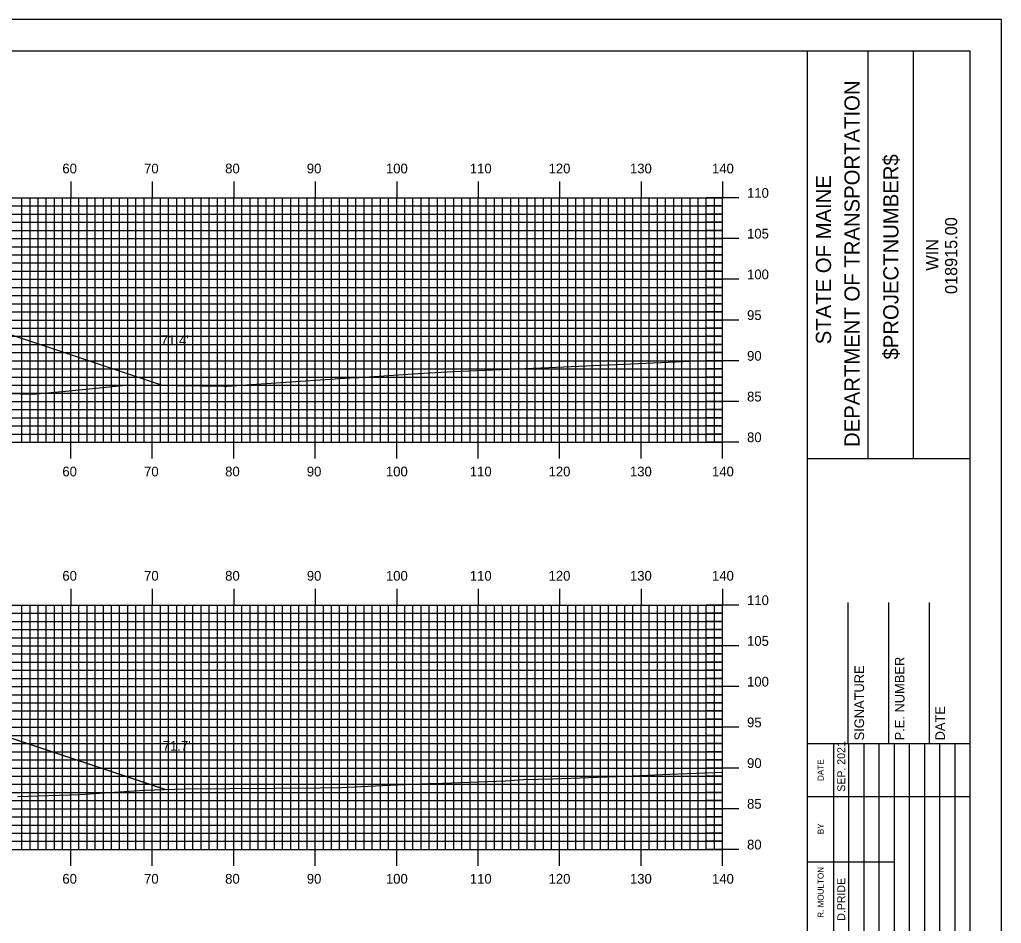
# Model space of a CAD drawing. Extents: x 1762184 to 1762528, y 442591 to 442811.
# Drawn here: x 1762404 to 1762524.5, y 442699.6 to 442810.5 of the extents above; entities that cross this region are included whole.
import ezdxf

# ---------------------------------------------------------------- set-up
doc = ezdxf.new("R2010")
doc.units = 0
for name, color, linetype in [('BORDER', 7, 'Continuous'), ('D_Roadway_Centerline', 7, 'Continuous'), ('D_Roadway_SlopeLines', 7, 'Continuous'), ('D_Text_Standard', 7, 'Continuous'), ('H_V ANNOTATION', 7, 'Continuous'), ('MAJOR', 7, 'Continuous'), ('MINOR', 7, 'Continuous'), ('PLOT BOUNDARY', 7, 'Continuous'), ('S_Roadway_Centerline', 7, 'Continuous')]:
    doc.layers.add(name, color=color, linetype=linetype)

msp = doc.modelspace()

# ---------------------------------------------------------------- linework, layer by layer
at = {"layer": 'BORDER'}
for p, q in [((1762500.67, 442596.67), (1762500.67, 442806.67)), ((1762508.12, 442756.66), (1762508.12, 442806.66)), ((1762513.71, 442756.66), (1762513.71, 442806.66)), ((1762500.67, 442756.65), (1762520.67, 442756.65)), ((1762505.67, 442721.67), (1762505.67, 442738.97)), ((1762510.67, 442721.67), (1762510.67, 442738.97)), ((1762515.67, 442721.67), (1762515.67, 442738.97)), ((1762500.67, 442721.67), (1762520.67, 442721.67))]:
    msp.add_line(p, q, dxfattribs=at)
msp.add_lwpolyline([(1762200.67, 442596.67), (1762520.67, 442596.67), (1762520.67, 442806.67), (1762200.67, 442806.67)], close=True, dxfattribs=at)
for points in [[(1762503.9, 442715.17), (1762503.9, 442721.67)], [(1762505.76, 442686.68), (1762505.76, 442721.67)], [(1762507.62, 442721.67), (1762507.62, 442686.68)], [(1762509.49, 442686.68), (1762509.49, 442721.67)], [(1762511.35, 442686.68), (1762511.35, 442721.67)], [(1762513.21, 442686.68), (1762513.21, 442721.67)], [(1762515.08, 442686.68), (1762515.08, 442721.67)], [(1762516.94, 442686.68), (1762516.94, 442721.67)], [(1762518.8, 442686.68), (1762518.8, 442721.67)], [(1762503.9, 442686.68), (1762503.9, 442720.26)], [(1762500.67, 442715.17), (1762520.67, 442715.17)], [(1762500.67, 442707.17), (1762503.9, 442707.17)], [(1762503.9, 442707.17), (1762511.35, 442707.17)]]:
    msp.add_lwpolyline(points, dxfattribs=at)
at = {"layer": 'D_Roadway_Centerline'}
for points in [[(1762382.28, 442778.76), (1762418.67, 442766.63), (1762421.63, 442765.65), (1762421.63, 442765.65)], [(1762382.27, 442729.27), (1762420.68, 442716.46), (1762421.95, 442716.04)]]:
    msp.add_lwpolyline(points, dxfattribs=at)
at = {"layer": 'D_Roadway_SlopeLines'}
for points in [[(1762370.27, 442781.77), (1762382.27, 442778.77), (1762421.63, 442765.65)], [(1762370.27, 442732.27), (1762382.27, 442729.27), (1762421.95, 442716.04)]]:
    msp.add_lwpolyline(points, dxfattribs=at)
at = {"layer": 'MAJOR'}
for p, q in [((1762410.27, 442790.67), (1762410.27, 442788.67)), ((1762420.27, 442790.67), (1762420.27, 442788.67)), ((1762430.27, 442790.67), (1762430.27, 442788.67)), ((1762440.27, 442790.67), (1762440.27, 442788.67)), ((1762450.27, 442790.67), (1762450.27, 442788.67)), ((1762460.27, 442790.67), (1762460.27, 442788.67)), ((1762470.27, 442790.67), (1762470.27, 442788.67)), ((1762480.27, 442790.67), (1762480.27, 442788.67)), ((1762490.27, 442790.67), (1762490.27, 442788.67)), ((1762210.27, 442788.67), (1762490.27, 442788.67)), ((1762210.27, 442788.67), (1762490.27, 442788.67)), ((1762410.27, 442758.67), (1762410.27, 442788.67)), ((1762420.27, 442758.67), (1762420.27, 442788.67)), ((1762430.27, 442758.67), (1762430.27, 442788.67)), ((1762440.27, 442758.67), (1762440.27, 442788.67)), ((1762450.27, 442758.67), (1762450.27, 442788.67)), ((1762460.27, 442758.67), (1762460.27, 442788.67)), ((1762470.27, 442758.67), (1762470.27, 442788.67)), ((1762480.27, 442758.67), (1762480.27, 442788.67)), ((1762492.27, 442788.67), (1762488.26, 442788.67)), ((1762490.27, 442758.67), (1762490.27, 442788.67)), ((1762490.27, 442758.67), (1762490.27, 442788.67)), ((1762210.27, 442783.67), (1762490.27, 442783.67)), ((1762492.27, 442783.67), (1762488.26, 442783.67)), ((1762210.27, 442778.67), (1762490.27, 442778.67)), ((1762492.27, 442778.67), (1762488.26, 442778.67)), ((1762210.27, 442773.67), (1762490.27, 442773.67)), ((1762492.27, 442773.67), (1762488.26, 442773.67)), ((1762210.27, 442768.67), (1762490.27, 442768.67)), ((1762492.27, 442768.67), (1762488.26, 442768.67)), ((1762210.27, 442763.67), (1762490.27, 442763.67)), ((1762492.27, 442763.67), (1762488.26, 442763.67)), ((1762210.27, 442758.67), (1762490.27, 442758.67)), ((1762210.27, 442758.67), (1762490.27, 442758.67)), ((1762410.27, 442756.66), (1762410.27, 442758.67)), ((1762420.27, 442756.66), (1762420.27, 442758.67)), ((1762430.27, 442756.66), (1762430.27, 442758.67)), ((1762440.27, 442756.66), (1762440.27, 442758.67)), ((1762450.27, 442756.66), (1762450.27, 442758.67)), ((1762460.27, 442756.66), (1762460.27, 442758.67)), ((1762470.27, 442756.66), (1762470.27, 442758.67)), ((1762480.27, 442756.66), (1762480.27, 442758.67)), ((1762492.27, 442758.67), (1762488.26, 442758.67)), ((1762490.27, 442756.66), (1762490.27, 442758.67)), ((1762410.27, 442740.67), (1762410.27, 442738.67)), ((1762420.27, 442740.67), (1762420.27, 442738.67)), ((1762430.27, 442740.67), (1762430.27, 442738.67)), ((1762440.27, 442740.67), (1762440.27, 442738.67)), ((1762450.27, 442740.67), (1762450.27, 442738.67)), ((1762460.27, 442740.67), (1762460.27, 442738.67)), ((1762470.27, 442740.67), (1762470.27, 442738.67)), ((1762480.27, 442740.67), (1762480.27, 442738.67)), ((1762490.27, 442740.67), (1762490.27, 442738.67)), ((1762210.27, 442738.67), (1762490.27, 442738.67)), ((1762210.27, 442738.67), (1762490.27, 442738.67)), ((1762410.27, 442708.67), (1762410.27, 442738.67)), ((1762420.27, 442708.67), (1762420.27, 442738.67)), ((1762430.27, 442708.67), (1762430.27, 442738.67)), ((1762440.27, 442708.67), (1762440.27, 442738.67)), ((1762450.27, 442708.67), (1762450.27, 442738.67)), ((1762460.27, 442708.67), (1762460.27, 442738.67)), ((1762470.27, 442708.67), (1762470.27, 442738.67)), ((1762480.27, 442708.67), (1762480.27, 442738.67)), ((1762492.27, 442738.67), (1762488.26, 442738.67)), ((1762490.27, 442708.67), (1762490.27, 442738.67)), ((1762490.27, 442708.67), (1762490.27, 442738.67)), ((1762210.27, 442733.67), (1762490.27, 442733.67)), ((1762492.27, 442733.67), (1762488.26, 442733.67)), ((1762210.27, 442728.67), (1762490.27, 442728.67)), ((1762492.27, 442728.67), (1762488.26, 442728.67)), ((1762210.27, 442723.67), (1762490.27, 442723.67)), ((1762492.27, 442723.67), (1762488.26, 442723.67)), ((1762210.27, 442718.67), (1762490.27, 442718.67)), ((1762492.27, 442718.67), (1762488.26, 442718.67)), ((1762210.27, 442713.67), (1762490.27, 442713.67)), ((1762492.27, 442713.67), (1762488.26, 442713.67)), ((1762210.27, 442708.67), (1762490.27, 442708.67)), ((1762210.27, 442708.67), (1762490.27, 442708.67)), ((1762410.27, 442706.66), (1762410.27, 442708.67)), ((1762420.27, 442706.66), (1762420.27, 442708.67)), ((1762430.27, 442706.66), (1762430.27, 442708.67)), ((1762440.27, 442706.66), (1762440.27, 442708.67)), ((1762450.27, 442706.66), (1762450.27, 442708.67)), ((1762460.27, 442706.66), (1762460.27, 442708.67)), ((1762470.27, 442706.66), (1762470.27, 442708.67)), ((1762480.27, 442706.66), (1762480.27, 442708.67)), ((1762492.27, 442708.67), (1762488.26, 442708.67)), ((1762490.27, 442706.66), (1762490.27, 442708.67))]:
    msp.add_line(p, q, dxfattribs=at)
at = {"layer": 'MINOR'}
for p, q in [((1762210.27, 442787.67), (1762490.27, 442787.67)), ((1762404.27, 442758.67), (1762404.27, 442788.67)), ((1762405.27, 442758.67), (1762405.27, 442788.67)), ((1762406.27, 442758.67), (1762406.27, 442788.67)), ((1762407.27, 442758.67), (1762407.27, 442788.67)), ((1762408.27, 442758.67), (1762408.27, 442788.67)), ((1762409.27, 442758.67), (1762409.27, 442788.67)), ((1762411.27, 442758.67), (1762411.27, 442788.67)), ((1762412.27, 442758.67), (1762412.27, 442788.67)), ((1762413.27, 442758.67), (1762413.27, 442788.67)), ((1762414.27, 442758.67), (1762414.27, 442788.67)), ((1762415.27, 442758.67), (1762415.27, 442788.67)), ((1762416.27, 442758.67), (1762416.27, 442788.67)), ((1762417.27, 442758.67), (1762417.27, 442788.67)), ((1762418.27, 442758.67), (1762418.27, 442788.67)), ((1762419.27, 442758.67), (1762419.27, 442788.67)), ((1762421.27, 442758.67), (1762421.27, 442788.67)), ((1762422.27, 442758.67), (1762422.27, 442788.67)), ((1762423.27, 442758.67), (1762423.27, 442788.67)), ((1762424.27, 442758.67), (1762424.27, 442788.67)), ((1762425.27, 442758.67), (1762425.27, 442788.67)), ((1762426.27, 442758.67), (1762426.27, 442788.67)), ((1762427.27, 442758.67), (1762427.27, 442788.67)), ((1762428.27, 442758.67), (1762428.27, 442788.67)), ((1762429.27, 442758.67), (1762429.27, 442788.67)), ((1762431.27, 442758.67), (1762431.27, 442788.67)), ((1762432.27, 442758.67), (1762432.27, 442788.67)), ((1762433.27, 442758.67), (1762433.27, 442788.67)), ((1762434.27, 442758.67), (1762434.27, 442788.67)), ((1762435.27, 442758.67), (1762435.27, 442788.67)), ((1762436.27, 442758.67), (1762436.27, 442788.67)), ((1762437.27, 442758.67), (1762437.27, 442788.67)), ((1762438.27, 442758.67), (1762438.27, 442788.67)), ((1762439.27, 442758.67), (1762439.27, 442788.67)), ((1762441.27, 442758.67), (1762441.27, 442788.67)), ((1762442.27, 442758.67), (1762442.27, 442788.67)), ((1762443.27, 442758.67), (1762443.27, 442788.67)), ((1762444.27, 442758.67), (1762444.27, 442788.67)), ((1762445.27, 442758.67), (1762445.27, 442788.67)), ((1762446.27, 442758.67), (1762446.27, 442788.67)), ((1762447.27, 442758.67), (1762447.27, 442788.67)), ((1762448.27, 442758.67), (1762448.27, 442788.67)), ((1762449.27, 442758.67), (1762449.27, 442788.67)), ((1762451.27, 442758.67), (1762451.27, 442788.67)), ((1762452.27, 442758.67), (1762452.27, 442788.67)), ((1762453.27, 442758.67), (1762453.27, 442788.67)), ((1762454.27, 442758.67), (1762454.27, 442788.67)), ((1762455.27, 442758.67), (1762455.27, 442788.67)), ((1762456.27, 442758.67), (1762456.27, 442788.67)), ((1762457.27, 442758.67), (1762457.27, 442788.67)), ((1762458.27, 442758.67), (1762458.27, 442788.67)), ((1762459.27, 442758.67), (1762459.27, 442788.67)), ((1762461.27, 442758.67), (1762461.27, 442788.67)), ((1762462.27, 442758.67), (1762462.27, 442788.67)), ((1762463.27, 442758.67), (1762463.27, 442788.67)), ((1762464.27, 442758.67), (1762464.27, 442788.67)), ((1762465.27, 442758.67), (1762465.27, 442788.67)), ((1762466.27, 442758.67), (1762466.27, 442788.67)), ((1762467.27, 442758.67), (1762467.27, 442788.67)), ((1762468.27, 442758.67), (1762468.27, 442788.67)), ((1762469.27, 442758.67), (1762469.27, 442788.67)), ((1762471.27, 442758.67), (1762471.27, 442788.67)), ((1762472.27, 442758.67), (1762472.27, 442788.67)), ((1762473.27, 442758.67), (1762473.27, 442788.67)), ((1762474.27, 442758.67), (1762474.27, 442788.67)), ((1762475.27, 442758.67), (1762475.27, 442788.67)), ((1762476.27, 442758.67), (1762476.27, 442788.67)), ((1762477.27, 442758.67), (1762477.27, 442788.67)), ((1762478.27, 442758.67), (1762478.27, 442788.67)), ((1762479.27, 442758.67), (1762479.27, 442788.67)), ((1762481.27, 442758.67), (1762481.27, 442788.67)), ((1762482.27, 442758.67), (1762482.27, 442788.67)), ((1762483.27, 442758.67), (1762483.27, 442788.67)), ((1762484.27, 442758.67), (1762484.27, 442788.67)), ((1762485.27, 442758.67), (1762485.27, 442788.67)), ((1762486.27, 442758.67), (1762486.27, 442788.67)), ((1762487.27, 442758.67), (1762487.27, 442788.67)), ((1762490.27, 442787.67), (1762488.26, 442787.67)), ((1762488.27, 442758.67), (1762488.27, 442788.67)), ((1762489.27, 442758.67), (1762489.27, 442788.67)), ((1762210.27, 442786.67), (1762490.27, 442786.67)), ((1762490.27, 442786.67), (1762488.26, 442786.67)), ((1762210.27, 442785.67), (1762490.27, 442785.67)), ((1762490.27, 442785.67), (1762488.26, 442785.67)), ((1762210.27, 442784.67), (1762490.27, 442784.67)), ((1762490.27, 442784.67), (1762488.26, 442784.67)), ((1762210.27, 442782.67), (1762490.27, 442782.67)), ((1762210.27, 442781.67), (1762490.27, 442781.67)), ((1762490.27, 442782.67), (1762488.26, 442782.67)), ((1762490.27, 442781.67), (1762488.26, 442781.67)), ((1762210.27, 442780.67), (1762490.27, 442780.67)), ((1762490.27, 442780.67), (1762488.26, 442780.67)), ((1762210.27, 442779.67), (1762490.27, 442779.67)), ((1762490.27, 442779.67), (1762488.26, 442779.67)), ((1762210.27, 442777.67), (1762490.27, 442777.67)), ((1762490.27, 442777.67), (1762488.26, 442777.67)), ((1762210.27, 442776.67), (1762490.27, 442776.67)), ((1762210.27, 442775.67), (1762490.27, 442775.67)), ((1762490.27, 442776.67), (1762488.26, 442776.67)), ((1762490.27, 442775.67), (1762488.26, 442775.67)), ((1762210.27, 442774.67), (1762490.27, 442774.67)), ((1762490.27, 442774.67), (1762488.26, 442774.67)), ((1762210.27, 442772.67), (1762490.27, 442772.67)), ((1762490.27, 442772.67), (1762488.26, 442772.67)), ((1762210.27, 442771.67), (1762490.27, 442771.67)), ((1762490.27, 442771.67), (1762488.26, 442771.67)), ((1762210.27, 442770.67), (1762490.27, 442770.67)), ((1762210.27, 442769.67), (1762490.27, 442769.67)), ((1762490.27, 442770.67), (1762488.26, 442770.67)), ((1762490.27, 442769.67), (1762488.26, 442769.67)), ((1762210.27, 442767.67), (1762490.27, 442767.67)), ((1762490.27, 442767.67), (1762488.26, 442767.67)), ((1762210.27, 442766.67), (1762490.27, 442766.67)), ((1762490.27, 442766.67), (1762488.26, 442766.67)), ((1762210.27, 442765.67), (1762490.27, 442765.67)), ((1762490.27, 442765.67), (1762488.26, 442765.67)), ((1762210.27, 442764.67), (1762490.27, 442764.67)), ((1762490.27, 442764.67), (1762488.26, 442764.67)), ((1762210.27, 442762.67), (1762490.27, 442762.67)), ((1762490.27, 442762.67), (1762488.26, 442762.67)), ((1762210.27, 442761.67), (1762490.27, 442761.67)), ((1762490.27, 442761.67), (1762488.26, 442761.67)), ((1762210.27, 442760.67), (1762490.27, 442760.67)), ((1762490.27, 442760.67), (1762488.26, 442760.67)), ((1762210.27, 442759.67), (1762490.27, 442759.67)), ((1762490.27, 442759.67), (1762488.26, 442759.67)), ((1762404.27, 442708.67), (1762404.27, 442738.67)), ((1762405.27, 442708.67), (1762405.27, 442738.67)), ((1762406.27, 442708.67), (1762406.27, 442738.67)), ((1762407.27, 442708.67), (1762407.27, 442738.67)), ((1762408.27, 442708.67), (1762408.27, 442738.67)), ((1762409.27, 442708.67), (1762409.27, 442738.67)), ((1762411.27, 442708.67), (1762411.27, 442738.67)), ((1762412.27, 442708.67), (1762412.27, 442738.67)), ((1762413.27, 442708.67), (1762413.27, 442738.67)), ((1762414.27, 442708.67), (1762414.27, 442738.67)), ((1762415.27, 442708.67), (1762415.27, 442738.67)), ((1762416.27, 442708.67), (1762416.27, 442738.67)), ((1762417.27, 442708.67), (1762417.27, 442738.67)), ((1762418.27, 442708.67), (1762418.27, 442738.67)), ((1762419.27, 442708.67), (1762419.27, 442738.67)), ((1762421.27, 442708.67), (1762421.27, 442738.67)), ((1762422.27, 442708.67), (1762422.27, 442738.67)), ((1762423.27, 442708.67), (1762423.27, 442738.67)), ((1762424.27, 442708.67), (1762424.27, 442738.67)), ((1762425.27, 442708.67), (1762425.27, 442738.67)), ((1762426.27, 442708.67), (1762426.27, 442738.67)), ((1762427.27, 442708.67), (1762427.27, 442738.67)), ((1762428.27, 442708.67), (1762428.27, 442738.67)), ((1762429.27, 442708.67), (1762429.27, 442738.67)), ((1762431.27, 442708.67), (1762431.27, 442738.67)), ((1762432.27, 442708.67), (1762432.27, 442738.67)), ((1762433.27, 442708.67), (1762433.27, 442738.67)), ((1762434.27, 442708.67), (1762434.27, 442738.67)), ((1762435.27, 442708.67), (1762435.27, 442738.67)), ((1762436.27, 442708.67), (1762436.27, 442738.67)), ((1762437.27, 442708.67), (1762437.27, 442738.67)), ((1762438.27, 442708.67), (1762438.27, 442738.67)), ((1762439.27, 442708.67), (1762439.27, 442738.67)), ((1762441.27, 442708.67), (1762441.27, 442738.67)), ((1762442.27, 442708.67), (1762442.27, 442738.67)), ((1762443.27, 442708.67), (1762443.27, 442738.67)), ((1762444.27, 442708.67), (1762444.27, 442738.67)), ((1762445.27, 442708.67), (1762445.27, 442738.67)), ((1762446.27, 442708.67), (1762446.27, 442738.67)), ((1762447.27, 442708.67), (1762447.27, 442738.67)), ((1762448.27, 442708.67), (1762448.27, 442738.67)), ((1762449.27, 442708.67), (1762449.27, 442738.67)), ((1762451.27, 442708.67), (1762451.27, 442738.67)), ((1762452.27, 442708.67), (1762452.27, 442738.67)), ((1762453.27, 442708.67), (1762453.27, 442738.67)), ((1762454.27, 442708.67), (1762454.27, 442738.67)), ((1762455.27, 442708.67), (1762455.27, 442738.67)), ((1762456.27, 442708.67), (1762456.27, 442738.67)), ((1762457.27, 442708.67), (1762457.27, 442738.67)), ((1762458.27, 442708.67), (1762458.27, 442738.67)), ((1762459.27, 442708.67), (1762459.27, 442738.67)), ((1762461.27, 442708.67), (1762461.27, 442738.67)), ((1762462.27, 442708.67), (1762462.27, 442738.67)), ((1762463.27, 442708.67), (1762463.27, 442738.67)), ((1762464.27, 442708.67), (1762464.27, 442738.67)), ((1762465.27, 442708.67), (1762465.27, 442738.67)), ((1762466.27, 442708.67), (1762466.27, 442738.67)), ((1762467.27, 442708.67), (1762467.27, 442738.67)), ((1762468.27, 442708.67), (1762468.27, 442738.67)), ((1762469.27, 442708.67), (1762469.27, 442738.67)), ((1762471.27, 442708.67), (1762471.27, 442738.67)), ((1762472.27, 442708.67), (1762472.27, 442738.67)), ((1762473.27, 442708.67), (1762473.27, 442738.67)), ((1762474.27, 442708.67), (1762474.27, 442738.67)), ((1762475.27, 442708.67), (1762475.27, 442738.67)), ((1762476.27, 442708.67), (1762476.27, 442738.67)), ((1762477.27, 442708.67), (1762477.27, 442738.67)), ((1762478.27, 442708.67), (1762478.27, 442738.67)), ((1762479.27, 442708.67), (1762479.27, 442738.67)), ((1762481.27, 442708.67), (1762481.27, 442738.67)), ((1762482.27, 442708.67), (1762482.27, 442738.67)), ((1762483.27, 442708.67), (1762483.27, 442738.67)), ((1762484.27, 442708.67), (1762484.27, 442738.67)), ((1762485.27, 442708.67), (1762485.27, 442738.67)), ((1762486.27, 442708.67), (1762486.27, 442738.67)), ((1762487.27, 442708.67), (1762487.27, 442738.67)), ((1762488.27, 442708.67), (1762488.27, 442738.67)), ((1762489.27, 442708.67), (1762489.27, 442738.67)), ((1762210.27, 442737.67), (1762490.27, 442737.67)), ((1762490.27, 442737.67), (1762488.26, 442737.67)), ((1762210.27, 442736.67), (1762490.27, 442736.67)), ((1762490.27, 442736.67), (1762488.26, 442736.67)), ((1762210.27, 442735.67), (1762490.27, 442735.67)), ((1762210.27, 442734.67), (1762490.27, 442734.67)), ((1762490.27, 442735.67), (1762488.26, 442735.67)), ((1762490.27, 442734.67), (1762488.26, 442734.67)), ((1762210.27, 442732.67), (1762490.27, 442732.67)), ((1762490.27, 442732.67), (1762488.26, 442732.67)), ((1762210.27, 442731.67), (1762490.27, 442731.67)), ((1762490.27, 442731.67), (1762488.26, 442731.67)), ((1762210.27, 442730.67), (1762490.27, 442730.67)), ((1762490.27, 442730.67), (1762488.26, 442730.67)), ((1762210.27, 442729.67), (1762490.27, 442729.67)), ((1762490.27, 442729.67), (1762488.26, 442729.67)), ((1762210.27, 442727.67), (1762490.27, 442727.67)), ((1762490.27, 442727.67), (1762488.26, 442727.67)), ((1762210.27, 442726.67), (1762490.27, 442726.67)), ((1762490.27, 442726.67), (1762488.26, 442726.67)), ((1762210.27, 442725.67), (1762490.27, 442725.67)), ((1762490.27, 442725.67), (1762488.26, 442725.67)), ((1762210.27, 442724.67), (1762490.27, 442724.67)), ((1762490.27, 442724.67), (1762488.26, 442724.67)), ((1762210.27, 442722.67), (1762490.27, 442722.67)), ((1762490.27, 442722.67), (1762488.26, 442722.67)), ((1762210.27, 442721.67), (1762490.27, 442721.67)), ((1762490.27, 442721.67), (1762488.26, 442721.67)), ((1762210.27, 442720.67), (1762490.27, 442720.67)), ((1762490.27, 442720.67), (1762488.26, 442720.67)), ((1762210.27, 442719.67), (1762490.27, 442719.67)), ((1762490.27, 442719.67), (1762488.26, 442719.67)), ((1762210.27, 442717.67), (1762490.27, 442717.67)), ((1762210.27, 442716.67), (1762490.27, 442716.67)), ((1762490.27, 442717.67), (1762488.26, 442717.67)), ((1762490.27, 442716.67), (1762488.26, 442716.67)), ((1762210.27, 442715.67), (1762490.27, 442715.67)), ((1762490.27, 442715.67), (1762488.26, 442715.67)), ((1762210.27, 442714.67), (1762490.27, 442714.67)), ((1762490.27, 442714.67), (1762488.26, 442714.67)), ((1762210.27, 442712.67), (1762490.27, 442712.67)), ((1762490.27, 442712.67), (1762488.26, 442712.67)), ((1762210.27, 442711.67), (1762490.27, 442711.67)), ((1762210.27, 442710.67), (1762490.27, 442710.67)), ((1762490.27, 442711.67), (1762488.26, 442711.67)), ((1762490.27, 442710.67), (1762488.26, 442710.67)), ((1762210.27, 442709.67), (1762490.27, 442709.67)), ((1762490.27, 442709.67), (1762488.26, 442709.67))]:
    msp.add_line(p, q, dxfattribs=at)
at = {"layer": 'PLOT BOUNDARY'}
msp.add_lwpolyline([(1762184.48, 442590.55), (1762524.48, 442590.55), (1762524.48, 442810.55), (1762184.48, 442810.55)], close=True, dxfattribs=at)
at = {"layer": 'S_Roadway_Centerline'}
for points in [[(1762398, 442764.77), (1762405.61, 442764.58), (1762410.06, 442764.98), (1762417.44, 442765.71), (1762429.08, 442765.53), (1762429.23, 442765.53), (1762429.44, 442765.54), (1762444.53, 442766.58), (1762445.67, 442766.63), (1762452.92, 442767.11), (1762454.35, 442767.2), (1762457.17, 442767.33), (1762468.95, 442767.84), (1762488.15, 442768.68), (1762488.55, 442768.69), (1762488.64, 442768.69), (1762488.77, 442768.7), (1762490.27, 442768.76)], [(1762403.74, 442715.17), (1762411.4, 442715.43), (1762419.28, 442715.95), (1762424.3, 442716.12), (1762440.86, 442716.23), (1762443.55, 442716.26), (1762445.85, 442716.42), (1762452.22, 442716.68), (1762454.34, 442716.78), (1762454.79, 442716.77), (1762463.61, 442717.11), (1762465.83, 442717.24), (1762469.45, 442717.36), (1762478.26, 442717.67), (1762483.78, 442717.91), (1762490.27, 442718.16)]]:
    msp.add_lwpolyline(points, dxfattribs=at)

# ---------------------------------------------------------------- texts
at = {"layer": 'BORDER'}
for s, height, p in [('DEPARTMENT OF TRANSPORTATION', 1.8635, (1762507.08, 442758.08)), ('$PROJECTNUMBER$', 1.8635, (1762511.85, 442768.82)), ('STATE OF MAINE', 1.8635, (1762503.58, 442770.69)), ('018915.00', 1.491, (1762519.06, 442776.86)), ('WIN', 1.491, (1762516.74, 442779.73)), ('P.E. NUMBER', 1.1811, (1762512.59, 442722.06)), ('SIGNATURE', 1.181, (1762507.63, 442722.06)), ('DATE', 1.181, (1762517.55, 442722.06)), ('SEP. 2021', 0.969, (1762505.31, 442715.76)), ('DATE', 0.743, (1762502.67, 442717.08)), ('BY', 0.743, (1762502.67, 442710.54)), ('R. MOULTON', 0.745, (1762502.67, 442700.28)), ('D.PRIDE', 0.969, (1762505.31, 442699.92))]:
    msp.add_text(s, height=height, rotation=90, dxfattribs=at).set_placement(p)
at = {"layer": 'D_Text_Standard'}
for s, p in [("71.4'", (1762421.32, 442770.59)), ("71.7'", (1762421.56, 442720.79))]:
    msp.add_text(s, height=1.2, dxfattribs=at).set_placement(p)
at = {"layer": 'H_V ANNOTATION'}
for s, p in [('60', (1762409.24, 442791.67)), ('70', (1762419.27, 442791.67)), ('80', (1762429.22, 442791.67)), ('90', (1762439.24, 442791.67)), ('100', (1762448.95, 442791.67)), ('110', (1762459.25, 442791.67)), ('120', (1762468.91, 442791.67)), ('130', (1762478.9, 442791.67)), ('140', (1762488.97, 442791.67)), ('110', (1762493.27, 442788.67)), ('105', (1762493.27, 442783.67)), ('100', (1762493.27, 442778.67)), ('95', (1762493.27, 442773.67)), ('90', (1762493.27, 442768.67)), ('85', (1762493.27, 442763.67)), ('80', (1762493.27, 442758.67)), ('60', (1762409.24, 442754.47)), ('70', (1762419.27, 442754.47)), ('80', (1762429.22, 442754.47)), ('90', (1762439.24, 442754.47)), ('100', (1762448.95, 442754.47)), ('110', (1762459.25, 442754.47)), ('120', (1762468.91, 442754.47)), ('130', (1762478.9, 442754.47)), ('140', (1762488.97, 442754.47)), ('60', (1762409.24, 442741.67)), ('70', (1762419.27, 442741.67)), ('80', (1762429.22, 442741.67)), ('90', (1762439.24, 442741.67)), ('100', (1762448.95, 442741.67)), ('110', (1762459.25, 442741.67)), ('120', (1762468.91, 442741.67)), ('130', (1762478.9, 442741.67)), ('140', (1762488.97, 442741.67)), ('110', (1762493.27, 442738.67)), ('105', (1762493.27, 442733.67)), ('100', (1762493.27, 442728.67)), ('95', (1762493.27, 442723.67)), ('90', (1762493.27, 442718.67)), ('85', (1762493.27, 442713.67)), ('80', (1762493.27, 442708.67)), ('60', (1762409.24, 442704.47)), ('70', (1762419.27, 442704.47)), ('80', (1762429.22, 442704.47)), ('90', (1762439.24, 442704.47)), ('100', (1762448.95, 442704.47)), ('110', (1762459.25, 442704.47)), ('120', (1762468.91, 442704.47)), ('130', (1762478.9, 442704.47)), ('140', (1762488.97, 442704.47))]:
    msp.add_text(s, height=1.2, dxfattribs=at).set_placement(p)

doc.saveas('drawing.dxf')
